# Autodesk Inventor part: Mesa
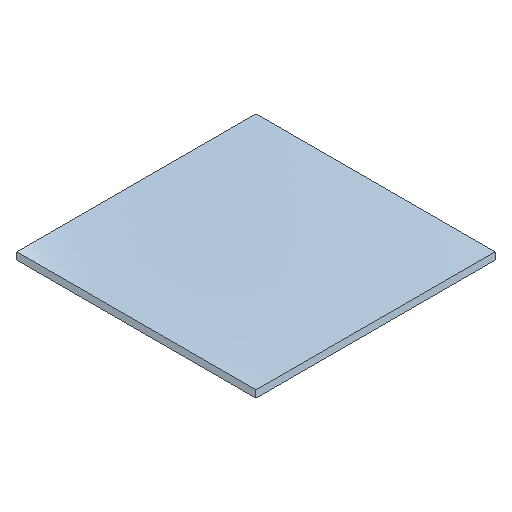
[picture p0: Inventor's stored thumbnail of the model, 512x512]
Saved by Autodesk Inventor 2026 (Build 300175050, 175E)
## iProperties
Created: 2025-06
Part Number: Mesa
Material: Genérico
Document SubType Name: Modeling
Designer: piero
Density: 1 g/cm^3
Appearance: Valor por defecto
Author: piero
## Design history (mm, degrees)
sketch "Boceto1"
  geometry: L1 (0, 0)-(500, 0); L2 (500, 0)-(500, -500); L3 (500, -500)-(0, -500); L4 (0, -500)-(0, 0)
  constraints: 8 end point, 2 parallel, 1 horizontal, 1 perpendicular
  dimensions: "d0" = 500 distance of L2.end L3.end; "d1" = 500 distance of L1.end L2.end
extrude "Extrusión1" new body sketch "Boceto1" distance "d2" = 20; taper "d3" = 0 deg
sketch "Boceto2"
  geometry: L1 (500, 20)-(0, 20) reference; L2 (0, 20)-(500, 20); L3 (500, 20)-(500, 0); L4 (500, 0)-(0, 0); L5 (0, 0)-(0, 20); 1 further point
  constraints: 8 end point, 2 parallel, 1 horizontal, 1 perpendicular
extrude "Extrusión2" join sketch "Boceto2" distance "d32" = 80; taper "d33" = 0 deg
sketch "Boceto3"
  geometry: L1 (0, 20)-(-580, 20) reference; L2 (0, 0)-(-580, 0) reference; L3 (0, 20)-(-580, 20); L4 (-580, 20)-(-580, 0); L5 (-580, 0)-(0, 0); L6 (0, 0)-(0, 20); 3 further points
  constraints: 8 end point, 2 parallel, 1 horizontal, 1 perpendicular
extrude "Extrusión3" join sketch "Boceto3" distance "d34" = 80; taper "d35" = 0 deg
sketch "Boceto4"
  geometry: L1 (0, 20)-(580, 20) reference; L2 (580, 20)-(580, 0) reference; L3 (0, 20)-(580, 20); L4 (580, 20)-(580, 0); L5 (580, 0)-(0, 0); L6 (0, 0)-(0, 20); 1 further point
  constraints: 8 end point, 2 parallel, 1 horizontal, 1 perpendicular
extrude "Extrusión4" join sketch "Boceto4" distance "d36" = 80; taper "d37" = 0 deg
sketch "Boceto5"
  geometry: L1 (0, 20)-(0, 0) reference; L2 (0, 0)-(660, 0) reference; L3 (0, 20)-(660, 20); L4 (660, 20)-(660, 0); L5 (660, 0)-(0, 0); L6 (0, 0)-(0, 20); 1 further point
  constraints: 8 end point, 2 parallel, 1 horizontal, 1 perpendicular
extrude "Extrusión5" join sketch "Boceto5" distance "d38" = 80; taper "d39" = 0 deg
node "Sólido1"
